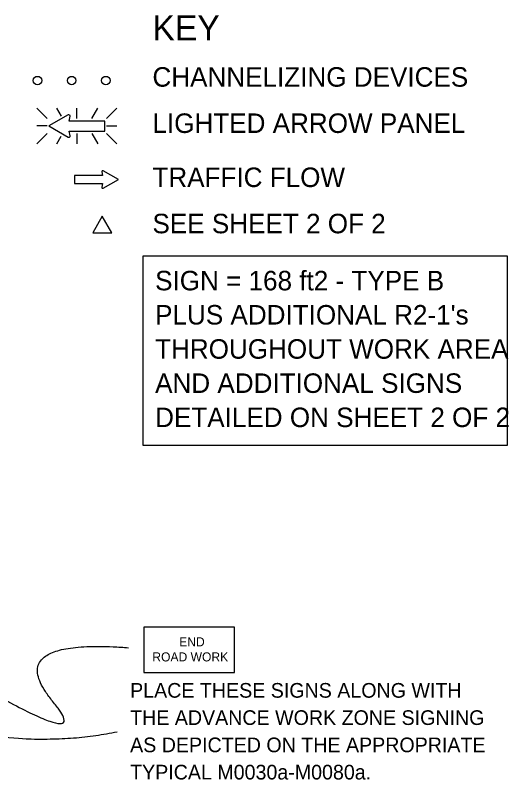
# Model space of a CAD drawing. Extents: x 16728 to 18475, y 6981 to 8243.
# Drawn here: x 17173.4 to 17408.8, y 7838.6 to 8203.1 of the extents above; entities that cross this region are included whole.
import ezdxf

# ---------------------------------------------------------------- set-up
doc = ezdxf.new("R2010")
doc.units = 0
for name, color, linetype in [('MT_SCRATCH_LEVEL_E', 7, 'Continuous'), ('TRAFFIC_SIGNS_PR', 7, 'Continuous'), ('TYPICAL_TEXT_DIMEN_EX', 7, 'Continuous'), ('TYPICAL_TEXT_DIMEN_PR', 7, 'Continuous')]:
    doc.layers.add(name, color=color, linetype=linetype)

msp = doc.modelspace()

# ---------------------------------------------------------------- linework, layer by layer
at = {"layer": 'MT_SCRATCH_LEVEL_E'}
for p, q in [((17222.55, 8124.78), (17215.31, 8128.89)), ((17222.55, 8124.78), (17215.31, 8128.89)), ((17214.94, 8126.63), (17201.69, 8126.63)), ((17201.69, 8126.63), (17201.69, 8122.89)), ((17214.94, 8126.63), (17201.69, 8126.63)), ((17201.69, 8126.63), (17201.69, 8122.89)), ((17214.63, 8128.41), (17214.94, 8126.63)), ((17214.63, 8128.41), (17214.94, 8126.63)), ((17201.69, 8122.89), (17214.94, 8122.89)), ((17201.69, 8122.89), (17214.94, 8122.89)), ((17214.94, 8122.89), (17214.63, 8121.11)), ((17214.94, 8122.89), (17214.63, 8121.11)), ((17215.31, 8120.63), (17222.55, 8124.78)), ((17215.31, 8120.63), (17222.55, 8124.78))]:
    msp.add_line(p, q, dxfattribs=at)
for centre, start, end in [((17215.09, 8128.48), 60.4248, 189.9638), ((17215.09, 8128.48), 60.4248, 189.9638), ((17215.09, 8121.04), 170.0362, 299.7731), ((17215.09, 8121.04), 170.0362, 299.7731)]:
    msp.add_arc(centre, 0.463, start, end, dxfattribs=at)
at = {"layer": 'TRAFFIC_SIGNS_PR'}
for p, q in [((17183.62, 8158.78), (17188.55, 8153.85)), ((17195.38, 8154.96), (17193.17, 8158.79)), ((17202.7, 8153.85), (17202.7, 8158.79)), ((17209.94, 8153.85), (17212.79, 8158.79)), ((17216.85, 8153.85), (17221.79, 8158.79)), ((17188.55, 8150.3), (17183.62, 8150.3)), ((17183.62, 8141.81), (17188.55, 8146.74)), ((17202.7, 8146.74), (17202.7, 8141.81)), ((17212.83, 8141.81), (17209.98, 8146.74)), ((17216.85, 8150.3), (17221.79, 8150.3)), ((17216.85, 8146.74), (17221.79, 8141.8)), ((17193.13, 8141.81), (17195.24, 8145.47))]:
    msp.add_line(p, q, dxfattribs=at)
for points in [[(17198.63, 8155.57), (17189.34, 8150.3), (17198.63, 8144.98)], [(17199.51, 8145.6), (17199.1, 8147.87), (17216.12, 8147.87), (17216.12, 8152.67), (17199.1, 8152.67), (17199.51, 8154.95)]]:
    msp.add_lwpolyline(points, dxfattribs=at)
msp.add_lwpolyline([(17234.69, 7889.65), (17277.89, 7889.65), (17277.89, 7911.25), (17234.69, 7911.25)], close=True, dxfattribs=at)
for centre in [(17183.96, 8171.98), (17200.26, 8171.98), (17216.56, 8171.98)]:
    msp.add_circle(centre, 2, dxfattribs=at)
for centre, radius, start, end in [((17198.92, 8155.05), 0.598, 350.7308, 118.8916), ((17198.92, 8145.5), 0.597, 241.4833, 9.9593)]:
    msp.add_arc(centre, radius, start, end, dxfattribs=at)
at = {"layer": 'TYPICAL_TEXT_DIMEN_EX'}
msp.add_lwpolyline([(17234.3, 8088.35), (17407.95, 8088.35), (17407.95, 7998.02), (17234.3, 7998.02)], close=True, dxfattribs=at)
at = {"layer": 'TYPICAL_TEXT_DIMEN_PR'}
msp.add_lwpolyline([(17214.83, 8107.27), (17210.31, 8099.43), (17219.36, 8099.43)], close=True, dxfattribs=at)
for points in [[(17221.94, 7861.33), (17166.62, 7849.44), (17000.13, 7906.03), (17038.24, 7978.99)], [(17126.63, 7901.54), (17216.29, 7845.78), (17166.16, 7906.16), (17227.39, 7901.54)]]:
    msp.add_open_spline(points, degree=2, dxfattribs=at)

# ---------------------------------------------------------------- texts
at = {"layer": 'TRAFFIC_SIGNS_PR'}
for s, height, p in [('END', 4.31, (17251.56, 7902.17)), ('ROAD WORK', 4.31, (17238.75, 7894.99)), ('PLACE THESE SIGNS ALONG WITH', 7, (17228.14, 7877.69)), ('THE ADVANCE WORK ZONE SIGNING', 7, (17228.14, 7864.69)), ('AS DEPICTED ON THE APPROPRIATE', 7, (17228.14, 7851.69)), ('TYPICAL M0030a-M0080a.', 7, (17228.14, 7838.69))]:
    msp.add_text(s, height=height, dxfattribs=at).set_placement(p)
at = {"layer": 'TYPICAL_TEXT_DIMEN_EX'}
for s, height, p in [('KEY', 12, (17238.8, 8191.09)), ('CHANNELIZING DEVICES', 9.3, (17238.8, 8169.04)), ('LIGHTED ARROW PANEL', 9.3, (17238.8, 8146.99)), ('TRAFFIC FLOW', 9.3, (17238.8, 8121.19)), ('SEE SHEET 2 OF 2', 9.3, (17238.8, 8099.14)), ('SIGN = 168 ft2 - TYPE B', 9.3, (17240.07, 8071.93)), ("PLUS ADDITIONAL R2-1's", 9.3, (17240.07, 8055.63)), ('THROUGHOUT WORK AREA', 9.3, (17240.07, 8039.33)), ('AND ADDITIONAL SIGNS', 9.3, (17240.07, 8023.03)), ('DETAILED ON SHEET 2 OF 2', 9.3, (17240.07, 8006.73))]:
    msp.add_text(s, height=height, dxfattribs=at).set_placement(p)

doc.saveas('drawing.dxf')
